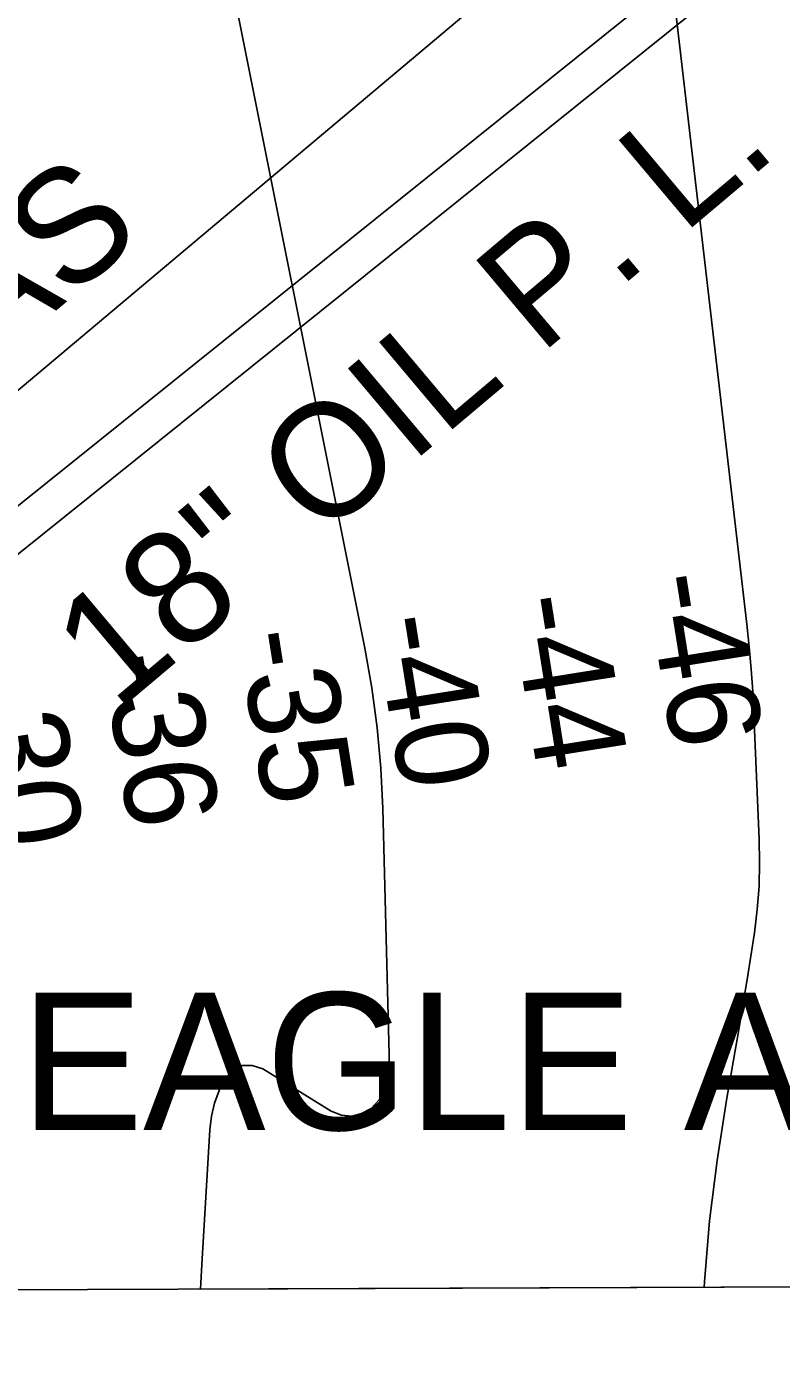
# Model space of a CAD drawing. Extents: x 3392644 to 3430565, y 576657 to 602123.
# Drawn here: x 3412894 to 3413444, y 582044 to 583022 of the extents above; entities that cross this region are included whole.
import ezdxf

# ---------------------------------------------------------------- set-up
doc = ezdxf.new("R2010")
doc.units = 0
for name, color, linetype in [('V-CHAN-NAID', 7, 'Continuous'), ('V-GRID-FRAM', 7, 'Continuous'), ('V-RIVR-RANG', 7, 'Continuous'), ('V-TOPO-DPTH', 7, 'Continuous'), ('V-TOPO-MAJR', 7, 'Continuous'), ('V-TOPO-MINR', 7, 'Continuous'), ('V-UTIL-IDEN', 7, 'Continuous'), ('V-UTIL-LINE', 7, 'Continuous')]:
    doc.layers.add(name, color=color, linetype=linetype)

msp = doc.modelspace()

# ---------------------------------------------------------------- linework, layer by layer
at = {"layer": 'V-GRID-FRAM'}
msp.add_lwpolyline([(3396720.28, 600227.69), (3428325.66, 600342.61), (3428399.71, 582159.31), (3396778.46, 582044.33), (3396720.28, 600227.69)], dxfattribs=at)
at = {"layer": 'V-TOPO-DPTH'}
msp.add_line((3413021.11, 582103.39), (3414824.64, 582109.94), dxfattribs=at)
msp.add_lwpolyline([(3413034.17, 583102.63), (3413140.69, 582570.01), (3413145.71, 582541.04), (3413149.74, 582511.95), (3413152.26, 582482.69), (3413153.78, 582453.32), (3413158.71, 582264.46), (3413157.74, 582256), (3413155.42, 582248.15), (3413151.08, 582241.21), (3413145.38, 582234.89), (3413138.34, 582231.07), (3413131.16, 582229.13), (3413123.78, 582230.02), (3413116.27, 582232.8), (3413066.41, 582263.68), (3413058.58, 582266.02), (3413051.31, 582266.05), (3413044.91, 582262.62), (3413039.07, 582256.89), (3413034.68, 582247.97), (3413031.17, 582238.79), (3413028.99, 582229.2), (3413027.71, 582219.34), (3413021.97, 582121.26), (3413021.11, 582103.39)], dxfattribs=at)
msp.add_lwpolyline([(3413034.17, 583102.63), (3413140.69, 582570.01), (3413145.71, 582541.04), (3413149.74, 582511.95), (3413152.26, 582482.69), (3413153.78, 582453.32), (3413158.71, 582264.46), (3413157.74, 582256), (3413155.42, 582248.15), (3413151.08, 582241.21), (3413145.38, 582234.89), (3413138.34, 582231.07), (3413131.16, 582229.13), (3413123.78, 582230.02), (3413116.27, 582232.8), (3413066.41, 582263.68), (3413058.58, 582266.02), (3413051.31, 582266.05), (3413044.91, 582262.62), (3413039.07, 582256.89), (3413034.68, 582247.97), (3413031.17, 582238.79), (3413028.99, 582229.2), (3413027.71, 582219.34), (3413021.97, 582121.26), (3413021.11, 582103.39)], dxfattribs=at)
at = {"layer": 'V-TOPO-MAJR'}
msp.add_lwpolyline([(3413388.01, 582104.72), (3413388.22, 582108.61), (3413391.83, 582152.9), (3413397.33, 582197), (3413404.07, 582240.97), (3413413.53, 582294.91), (3413416.42, 582311.82), (3413419.22, 582328.75), (3413421.89, 582345.71), (3413424.47, 582362.67), (3413426.49, 582379.68), (3413427.86, 582396.71), (3413428.27, 582413.8), (3413428.04, 582430.92), (3413424.2, 582521.92), (3413423.33, 582538.3), (3413422.22, 582554.66), (3413420.74, 582570.99), (3413419.03, 582587.31), (3413370.1, 583007.5), (3413363.04, 583067.71)], dxfattribs=at)
at = {"layer": 'V-TOPO-MINR'}
msp.add_lwpolyline([(3413021.11, 582103.39), (3413021.97, 582121.26), (3413027.71, 582219.34), (3413028.99, 582229.2), (3413031.17, 582238.79), (3413034.68, 582247.97), (3413039.07, 582256.89), (3413044.91, 582262.62), (3413051.31, 582266.05), (3413058.58, 582266.02), (3413066.41, 582263.68), (3413116.27, 582232.8), (3413123.78, 582230.02), (3413131.16, 582229.13), (3413138.34, 582231.07), (3413145.38, 582234.89), (3413151.08, 582241.21), (3413155.42, 582248.15), (3413157.74, 582256), (3413158.71, 582264.46), (3413153.78, 582453.32), (3413152.26, 582482.69), (3413149.74, 582511.95), (3413145.71, 582541.04), (3413140.69, 582570.01), (3413034.17, 583102.63)], dxfattribs=at)
at = {"layer": 'V-UTIL-LINE'}
for p, q in [((3412297.94, 582200.06), (3415100.62, 584449.07)), ((3412328.89, 582189.74), (3415131.57, 584438.76))]:
    msp.add_line(p, q, dxfattribs=at)
msp.add_lwpolyline([(3412089.87, 582100), (3412530.99, 582457.84), (3414603.59, 584199.19), (3415068.56, 584289.48), (3415163.54, 584253.48), (3416142.94, 584475.33), (3415963.69, 585213.99)], dxfattribs=at)

# ---------------------------------------------------------------- texts
at = {"layer": 'V-CHAN-NAID'}
msp.add_text('EAGLE ASPHALT (167.5)', height=100, dxfattribs=at).set_placement((3412890.05, 582219.21))
at = {"layer": 'V-RIVR-RANG'}
for s, p in [('-46', (3413344.97, 582621.7)), ('-44', (3413246.23, 582605.94)), ('-40', (3413147.27, 582591.47)), ('-35', (3413047.77, 582580.39)), ('-36', (3412949.23, 582563.32)), ('-30', (3412850.32, 582548.59))]:
    msp.add_text(s, height=67, rotation=279.06297, dxfattribs=at).set_placement(p)
at = {"layer": 'V-UTIL-IDEN'}
for s, height, rotation, p in [('18" OIL P. L.', 82.9998, 40.10917, (3412959.88, 582523.14)), ('TEXAS', 83, 39.96166, (3412701.93, 582636.44))]:
    msp.add_text(s, height=height, rotation=rotation, dxfattribs=at).set_placement(p)

doc.saveas('drawing.dxf')
